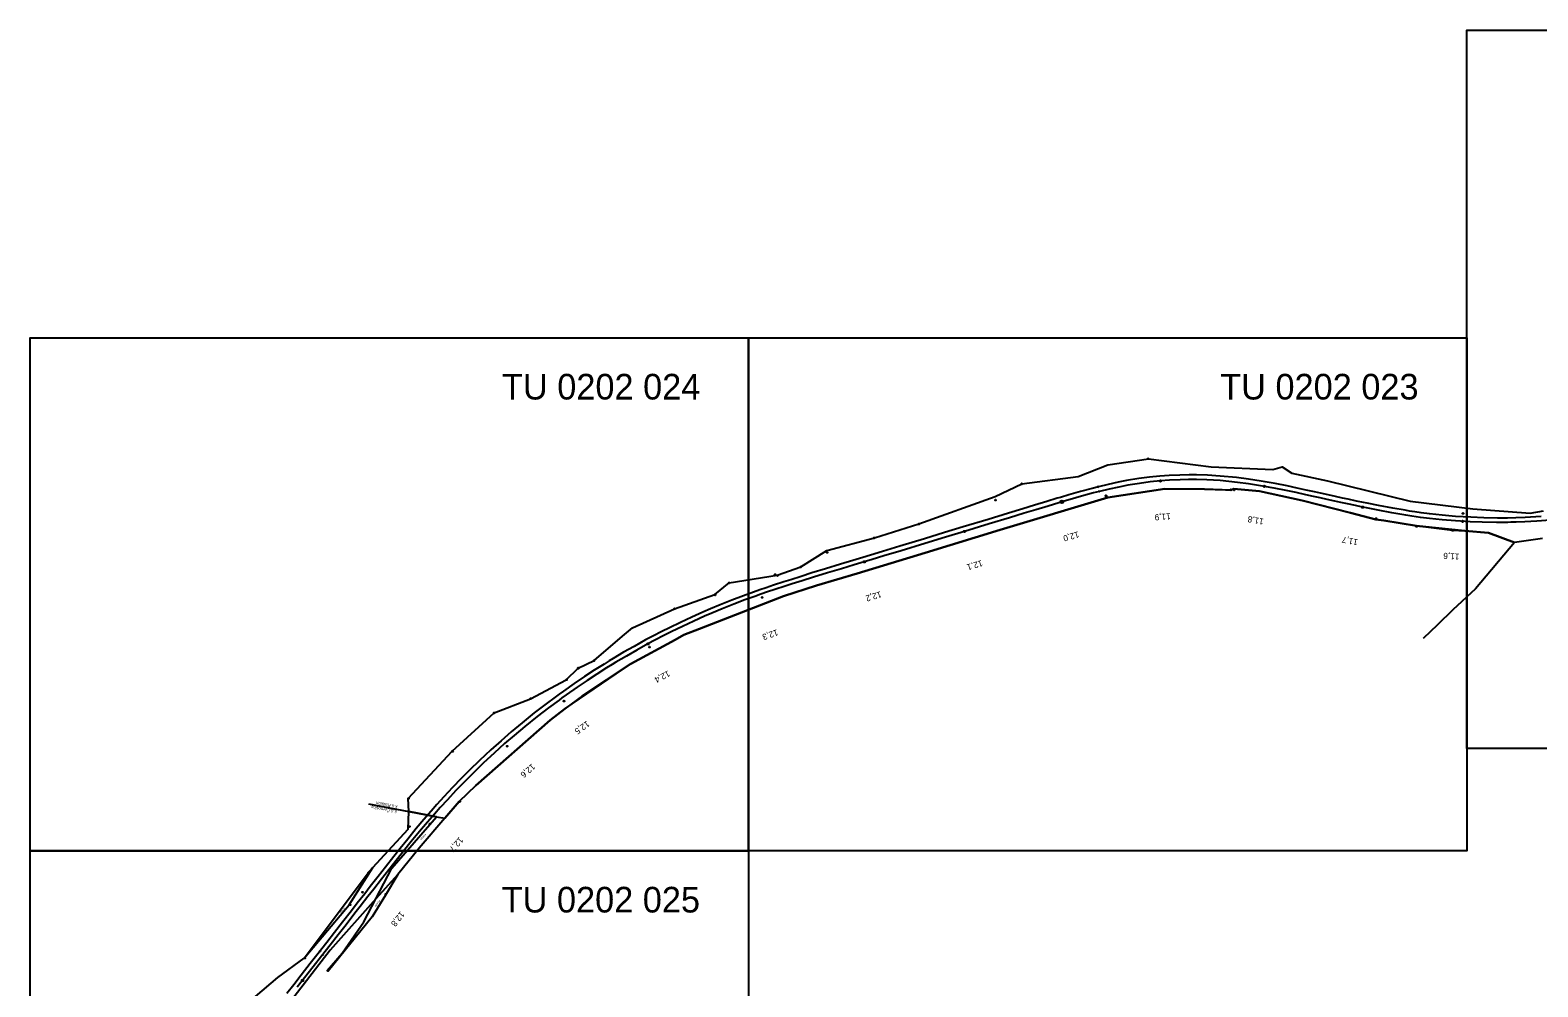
# Model space of a CAD drawing. Extents: x -768800 to -748700, y -1061452 to -1051366.
# Drawn here: x -751300 to -749831, y -1055132 to -1054200 of the extents above; entities that cross this region are included whole.
import ezdxf

# ---------------------------------------------------------------- set-up
doc = ezdxf.new("R2010")
doc.units = 0
for name, color, linetype in [('Vrstva 1', 7, 'Continuous'), ('Vrstva 2', 7, 'Continuous'), ('Vrstva 53', 7, 'Continuous'), ('Vrstva 55', 7, 'Continuous'), ('Vrstva 57', 7, 'Continuous'), ('Vrstva 7', 7, 'Continuous')]:
    doc.layers.add(name, color=color, linetype=linetype)

msp = doc.modelspace()

# ---------------------------------------------------------------- linework, layer by layer
at = {"layer": 'Vrstva 1'}
for points in [[(-749900, -1054900), (-749900, -1054200), (-749400, -1054200), (-749400, -1054900), (-749900, -1054900)], [(-751300, -1055000), (-751300, -1054500), (-750600, -1054500), (-750600, -1055000), (-751300, -1055000)], [(-750600, -1055000), (-750600, -1054500), (-749900, -1054500), (-749900, -1055000), (-750600, -1055000)], [(-749827.5, -1054674), (-749832.7, -1054674.4), (-749843.2, -1054674.9), (-749852.2, -1054675.3), (-749860.3, -1054675.5), (-749870.1, -1054675.5), (-749883.3, -1054675.3), (-749896.2, -1054674.8), (-749910.9, -1054673.9), (-749923.9, -1054672.8), (-749936.3, -1054671.4), (-749944.5, -1054670.3), (-749950.8, -1054669.4), (-749953.1, -1054669.1), (-749955.7, -1054668.7), (-749960.2, -1054668), (-749972.1, -1054666), (-749985.9, -1054663.4), (-749997.1, -1054661.2), (-750000.8, -1054660.4), (-750007.6, -1054659), (-750015.5, -1054657.3), (-750021, -1054656.1), (-750027.8, -1054654.6), (-750035, -1054653), (-750042.5, -1054651.3), (-750048.3, -1054650), (-750056.4, -1054648.3), (-750065.2, -1054646.4), (-750075.2, -1054644.3), (-750086.9, -1054642), (-750096.5, -1054640.3), (-750100.3, -1054639.6), (-750112.6, -1054637.7), (-750124.3, -1054636.1), (-750140.2, -1054634.6), (-750152.8, -1054633.8), (-750163.5, -1054633.4), (-750170.7, -1054633.4), (-750179.8, -1054633.6), (-750190, -1054634.1), (-750199.2, -1054634.7), (-750209.2, -1054635.8), (-750219.6, -1054637.1), (-750231.5, -1054639.1), (-750239.8, -1054640.7), (-750249.4, -1054642.8), (-750259, -1054645.1), (-750265, -1054646.6), (-750276.3, -1054649.7), (-750287.8, -1054653), (-750296, -1054655.4), (-750299.1, -1054656.3), (-750309.3, -1054659.4), (-750321.3, -1054663.1), (-750332.7, -1054666.5), (-750346.7, -1054670.8), (-750366.5, -1054676.8), (-750390.9, -1054684.2), (-750409, -1054689.7), (-750428.6, -1054695.7), (-750452.5, -1054703), (-750469.5, -1054708.1), (-750481.1, -1054711.7), (-750488.6, -1054714), (-750498.4, -1054716.9), (-750510.3, -1054720.6), (-750525.1, -1054725.1), (-750538.1, -1054729.1), (-750548.8, -1054732.4), (-750558.8, -1054735.6), (-750565.7, -1054737.8), (-750575.7, -1054741.1), (-750582.8, -1054743.5), (-750589, -1054745.6), (-750595.2, -1054747.8), (-750604.9, -1054751.3), (-750616.1, -1054755.6), (-750627.7, -1054760.2), (-750637.1, -1054764.1), (-750644.5, -1054767.3), (-750655.2, -1054772.1), (-750666.2, -1054777.2), (-750677.1, -1054782.5), (-750684.3, -1054786.1), (-750693.3, -1054790.7), (-750700.2, -1054794.4), (-750711.4, -1054800.6), (-750721.7, -1054806.4), (-750731.8, -1054812.4), (-750735.7, -1054814.8), (-750740.6, -1054817.8), (-750750.3, -1054823.9), (-750759.7, -1054830.1), (-750769.8, -1054836.9), (-750780.3, -1054844.2), (-750784.5, -1054847.2), (-750787, -1054849), (-750798.5, -1054857.6), (-750808.7, -1054865.5), (-750820.7, -1054875.2), (-750831.1, -1054883.9), (-750841.1, -1054892.6), (-750851, -1054901.4), (-750862, -1054911.7), (-750871.8, -1054921.3), (-750880, -1054929.5), (-750888.4, -1054938.2), (-750896.8, -1054947.2), (-750903.7, -1054954.8), (-750909.3, -1054961.2), (-750916.4, -1054969.4), (-750923.7, -1054978.1), (-750932.1, -1054988.4), (-750939.5, -1054997.7), (-750945.7, -1055005.4), (-750953.7, -1055015.7), (-750960.9, -1055024.9), (-750968.5, -1055034.6), (-750974, -1055041.8), (-750981.2, -1055051), (-750986.9, -1055058.3), (-750995.5, -1055069.3), (-751003.5, -1055079.5), (-751011, -1055089.1), (-751019.3, -1055099.9), (-751027, -1055109.7), (-751035.9, -1055121.2), (-751043.2, -1055130.4), (-751050, -1055139.1)], [(-749818.6, -1054677.6), (-749831.8, -1054678.6), (-749843.4, -1054679.3), (-749851.9, -1054679.6), (-749857.2, -1054679.7), (-749860, -1054679.8), (-749862.2, -1054679.8), (-749871.2, -1054679.9), (-749884.9, -1054679.7), (-749896.6, -1054679.3), (-749911, -1054678.4), (-749923.9, -1054677.3), (-749936.5, -1054675.9), (-749945.2, -1054674.9), (-749953.6, -1054673.6), (-749959.4, -1054672.8), (-749973.2, -1054670.4), (-749986.4, -1054668), (-749997.6, -1054665.7), (-750001.7, -1054664.9), (-750008.5, -1054663.4), (-750016.2, -1054661.8), (-750022.6, -1054660.4), (-750028.7, -1054659), (-750036, -1054657.4), (-750043, -1054655.8), (-750049.4, -1054654.4), (-750056.9, -1054652.8), (-750066.4, -1054650.7), (-750075.9, -1054648.7), (-750087.6, -1054646.4), (-750097.2, -1054644.7), (-750100.9, -1054644), (-750112.6, -1054642.2), (-750123.4, -1054640.8), (-750140.5, -1054639.1), (-750153.2, -1054638.3), (-750163.4, -1054638.1), (-750171.1, -1054638), (-750179.4, -1054638.2), (-750189.6, -1054638.7), (-750198.5, -1054639.4), (-750208.4, -1054640.4), (-750218.8, -1054641.8), (-750230.2, -1054643.6), (-750239.2, -1054645.4), (-750248.4, -1054647.3), (-750257.9, -1054649.6), (-750263.7, -1054651.1), (-750275.4, -1054654.3), (-750286.6, -1054657.5), (-750294.7, -1054659.9), (-750297.7, -1054660.8), (-750308.1, -1054663.9), (-750320, -1054667.5), (-750331.3, -1054670.9), (-750345.7, -1054675.3), (-750365.3, -1054681.3), (-750389.5, -1054688.6), (-750407.9, -1054694.2), (-750428.3, -1054700.4), (-750451.3, -1054707.4), (-750468.2, -1054712.5), (-750479.6, -1054715.9), (-750487.2, -1054718.2), (-750496.9, -1054721.1), (-750509.3, -1054724.9), (-750523, -1054729.1), (-750536.8, -1054733.3), (-750547.8, -1054736.7), (-750557.4, -1054739.7), (-750564.1, -1054741.8), (-750574.4, -1054745.2), (-750581.5, -1054747.6), (-750587.8, -1054749.8), (-750593.7, -1054751.9), (-750603.4, -1054755.4), (-750614.4, -1054759.5), (-750625.8, -1054764.1), (-750635.6, -1054768.2), (-750642.8, -1054771.3), (-750653.4, -1054776), (-750664.2, -1054781.1), (-750674.7, -1054786.2), (-750682.6, -1054790.1), (-750691.4, -1054794.6), (-750698.2, -1054798.3), (-750708.8, -1054804.2), (-750719, -1054810), (-750729.2, -1054816), (-750732.8, -1054818.2), (-750738.2, -1054821.5), (-750747.9, -1054827.7), (-750757.3, -1054833.8), (-750767.1, -1054840.5), (-750777.8, -1054848), (-750781.8, -1054850.8), (-750784.6, -1054852.9), (-750795, -1054860.6), (-750806, -1054869.1), (-750818, -1054878.7), (-750828.3, -1054887.4), (-750837.6, -1054895.4), (-750847.9, -1054904.7), (-750858.2, -1054914.2), (-750868.7, -1054924.4), (-750876.7, -1054932.5), (-750885.1, -1054941.1), (-750893.4, -1054950.1), (-750900.3, -1054957.6), (-750906.1, -1054964.2), (-750912.9, -1054972), (-750920.5, -1054981), (-750928.6, -1054990.9), (-750936.2, -1055000.3), (-750942.1, -1055007.8), (-750950.4, -1055018.4), (-750957.7, -1055027.6), (-750965.2, -1055037.3), (-750970.8, -1055044.4), (-750978.4, -1055054.3), (-750983.5, -1055060.8), (-750992.2, -1055071.9), (-751000, -1055081.9), (-751007.8, -1055091.9), (-751016, -1055102.5), (-751024.1, -1055112.8), (-751032.5, -1055123.6), (-751039.7, -1055132.9)], [(-751300, -1055500), (-751300, -1055000), (-750600, -1055000), (-750600, -1055500), (-751300, -1055500)]]:
    msp.add_lwpolyline(points, dxfattribs=at)
at = {"layer": 'Vrstva 53'}
for p, q in [((-750210.4, -1054617.7), (-750210.5, -1054617.7)), ((-750333.5, -1054642.2), (-750333.6, -1054642.3)), ((-750251.6, -1054653.8), (-750251.7, -1054653.8)), ((-750129.9, -1054648), (-750130, -1054648)), ((-750126.7, -1054648.1), (-750126.8, -1054648.1)), ((-750359.2, -1054658.1), (-750359.3, -1054658.1)), ((-750433.9, -1054681.4), (-750434, -1054681.4)), ((-749988.2, -1054676.1), (-749988.3, -1054676.1)), ((-749948.9, -1054683.6), (-749949, -1054683.6)), ((-750477.4, -1054694.9), (-750477.5, -1054694.9)), ((-750477.5, -1054694.9), (-750477.4, -1054694.9)), ((-749913.7, -1054687.5), (-749913.8, -1054687.5)), ((-750523.3, -1054709), (-750523.4, -1054709)), ((-750548.9, -1054723.2), (-750549, -1054723.2)), ((-750618.8, -1054738.7), (-750618.9, -1054738.7)), ((-750574.1, -1054730.7), (-750574, -1054730.7)), ((-750571.8, -1054731.5), (-750571.9, -1054731.6)), ((-750632.5, -1054750.4), (-750632.6, -1054750.4)), ((-750672.1, -1054763.9), (-750672.2, -1054763.9)), ((-750750.2, -1054814.5), (-750750.3, -1054814.5)), ((-750777.4, -1054833), (-750777.4, -1054833.1)), ((-750766.1, -1054821.8), (-750766, -1054821.8)), ((-750765.8, -1054822), (-750765.9, -1054822.1)), ((-750812.2, -1054851.4), (-750812.3, -1054851.5)), ((-750761.6, -1054849.1), (-750761.7, -1054849.2)), ((-750847.8, -1054865.4), (-750847.8, -1054865.5)), ((-750888.4, -1054902.9), (-750888.4, -1054902.9)), ((-750931.4, -1054948.9), (-750931.5, -1054949)), ((-750931.1, -1054961.5), (-750931.1, -1054961.6)), ((-750881.3, -1054951.9), (-750881.3, -1054952)), ((-750930.4, -1054976.2), (-750930.5, -1054976.3)), ((-750970.2, -1055021.5), (-750970.2, -1055021.5)), ((-750988.2, -1055052.4), (-750988.2, -1055052.5)), ((-750953.3, -1055042.2), (-750953.4, -1055042.3)), ((-751032.3, -1055104.5), (-751032.4, -1055104.5))]:
    msp.add_line(p, q, dxfattribs=at)
for points in [[(-750931.1, -1054961.4), (-750931.6, -1054949), (-750888.6, -1054902.8), (-750847.9, -1054865.4), (-750812.3, -1054851.7), (-750777.6, -1054833.1), (-750766, -1054821.7), (-750750.4, -1054814.4), (-750722.9, -1054790.6), (-750713, -1054782.4), (-750672.1, -1054763.9), (-750632.9, -1054750.2), (-750618.8, -1054738.6), (-750571.9, -1054731.3), (-750549.1, -1054723.1), (-750523.8, -1054707.3), (-750477.3, -1054694.7), (-750433.9, -1054681.3), (-750359.5, -1054654.7), (-750333.6, -1054642.1), (-750278.8, -1054634.9), (-750249.7, -1054623.8), (-750210.3, -1054617.7), (-750149, -1054625.5), (-750088.9, -1054628.2), (-750079.8, -1054625.6), (-750070.6, -1054631.7), (-750035.6, -1054639.4), (-749955.1, -1054659), (-749894.2, -1054666.6), (-749838.3, -1054670.7), (-749825.1, -1054668.6)], [(-749826.3, -1054695.4), (-749853.4, -1054699.5), (-749878.7, -1054689.8), (-749901.9, -1054688.1), (-749939.8, -1054684.1), (-749948.9, -1054683), (-749980.7, -1054678), (-749988.6, -1054676.8), (-750013.3, -1054670.4), (-750060.3, -1054658.4), (-750102.1, -1054649.2), (-750127, -1054647), (-750130, -1054648.4), (-750155.7, -1054647.4), (-750194.3, -1054647.2), (-750249.9, -1054655.4), (-750354.8, -1054686.9), (-750427.8, -1054709.4), (-750494, -1054729.6), (-750533.8, -1054741.3), (-750566, -1054751.8), (-750647.6, -1054783.5), (-750663.1, -1054789.5), (-750671.5, -1054794.1), (-750714.5, -1054817.7), (-750761.6, -1054848.9), (-750778.8, -1054861.6), (-750793.4, -1054872.4), (-750865.8, -1054936.1), (-750881.8, -1054951.7), (-750895.8, -1054968.2)], [(-751080.3, -1055141.9), (-751058.6, -1055123.3), (-751033.1, -1055104.6), (-750969.3, -1055019.7), (-750966, -1055016.1), (-750931.7, -1054978.8), (-750931.1, -1054961.4)], [(-750895.8, -1054968.2), (-750920.9, -1054997.3), (-750941.6, -1055022.9), (-750953.8, -1055043.1), (-750966.8, -1055064.2), (-751009.7, -1055117.3), (-751010.7, -1055116.4), (-750996.1, -1055099.7), (-750974.7, -1055069.2), (-750963, -1055046.8), (-751007.6, -1055096.7), (-751044.9, -1055145)]]:
    msp.add_lwpolyline(points, dxfattribs=at)
for centre in [(-750210.4, -1054617.7), (-750333.6, -1054642.2), (-750251.6, -1054653.8), (-750129.9, -1054648), (-750126.8, -1054648.1), (-750359.3, -1054658.1), (-750434, -1054681.4), (-749988.2, -1054676.1), (-749948.9, -1054683.6), (-750477.5, -1054694.9), (-750477.5, -1054694.9), (-749913.8, -1054687.5), (-750523.4, -1054709), (-750574, -1054730.7), (-750549, -1054723.2), (-750618.8, -1054738.7), (-750571.8, -1054731.6), (-750632.5, -1054750.4), (-750672.1, -1054763.9), (-750750.3, -1054814.5), (-750777.4, -1054833.1), (-750766, -1054821.8), (-750765.9, -1054822.1), (-750812.2, -1054851.5), (-750761.7, -1054849.2), (-750847.8, -1054865.5), (-750888.4, -1054902.9), (-750931.4, -1054949), (-750931.1, -1054961.6), (-750881.3, -1054951.9), (-750930.4, -1054976.3), (-750970.2, -1055021.5), (-750988.2, -1055052.4), (-750953.3, -1055042.2), (-751032.4, -1055104.5)]:
    msp.add_circle(centre, 0.499, dxfattribs=at)
at = {"layer": 'Vrstva 55'}
for p, q in [((-750904, -1054966.6), (-750931.1, -1054961.4)), ((-750931.1, -1054961.4), (-750904, -1054966.6)), ((-750941.6, -1055022.9), (-750963, -1055046.8))]:
    msp.add_line(p, q, dxfattribs=at)
for points in [[(-750904, -1054966.6), (-750895.8, -1054968.2), (-750881.8, -1054951.7), (-750865.8, -1054936.1), (-750793.4, -1054872.4), (-750778.8, -1054861.6), (-750714.5, -1054817.7), (-750671.5, -1054794.1), (-750663.1, -1054789.5), (-750647.6, -1054783.5), (-750566, -1054751.8), (-750533.8, -1054741.3), (-750494, -1054729.6), (-750427.8, -1054709.4), (-750354.8, -1054686.9), (-750249.9, -1054655.4), (-750194.3, -1054647.2), (-750155.7, -1054647.4), (-750135.2, -1054648.2), (-750130, -1054648.4), (-750127, -1054647), (-750102.1, -1054649.2), (-750060.3, -1054658.4), (-750013.3, -1054670.4), (-749988.6, -1054676.8), (-749980.7, -1054678), (-749948.9, -1054683), (-749939.8, -1054684.1), (-749913.8, -1054687.3), (-749901.9, -1054688.1), (-749878.7, -1054689.8), (-749853.4, -1054699.5), (-749891.5, -1054744.6), (-749913.6, -1054764.9), (-749928.5, -1054779.6), (-749942.6, -1054792.9)], [(-750970.3, -1054954.2), (-750931.1, -1054961.4)], [(-750963, -1055046.8), (-750947.6, -1055016.9), (-750904, -1054966.6), (-750895.8, -1054968.2)], [(-751033.1, -1055104.6), (-750989.1, -1055052.6), (-750966, -1055016.1)]]:
    msp.add_lwpolyline(points, dxfattribs=at)
at = {"layer": 'Vrstva 7'}
for p, q in [((-749903.7, -1054671), (-749903.8, -1054671)), ((-750586.5, -1054752.9), (-750586.6, -1054752.9)), ((-750696.5, -1054801.3), (-750696.4, -1054801.3)), ((-750779.8, -1054853.9), (-750779.9, -1054854)), ((-750835.2, -1054897.9), (-750835.3, -1054898)), ((-750910.4, -1054973.8), (-750910.5, -1054973.9)), ((-750976, -1055040.1), (-750976.1, -1055040.2))]:
    msp.add_line(p, q, dxfattribs=at)
for centre, radius in [((-750198.6, -1054639.4), 0.75), ((-750097.4, -1054644.7), 0.75), ((-750294.6, -1054659.8), 1.25), ((-750294.6, -1054659.8), 0.752), ((-750001.6, -1054664.9), 0.75), ((-749903.7, -1054671), 0.5), ((-749904.1, -1054678.8), 0.75), ((-750389.5, -1054688.6), 0.75), ((-750487.2, -1054718.2), 0.75), ((-750586.6, -1054752.9), 0.5), ((-750698.1, -1054798.2), 0.75), ((-750696.5, -1054801.3), 0.5), ((-750779.8, -1054853.9), 0.5), ((-750835.2, -1054897.9), 0.5), ((-750910.5, -1054973.8), 0.5), ((-750976, -1055040.2), 0.5), ((-751034.6, -1055126.3), 0.75)]:
    msp.add_circle(centre, radius, dxfattribs=at)

# ---------------------------------------------------------------- texts
at = {"layer": 'Vrstva 1'}
for s, rotation, p in [('2', 194.3596, (-750258.7, -1054643.7)), ('1', 194.2843, (-750257.7, -1054648.3)), ('2', 232.0698, (-751017.8, -1055096.2)), ('1', 232.0637, (-751015.2, -1055100))]:
    msp.add_text(s, height=2.5, rotation=rotation, dxfattribs=at).set_placement(p)
at = {"layer": 'Vrstva 2'}
for s, p in [('TU 0202 024', (-750840.2, -1054560)), ('TU 0202 023', (-750140.3, -1054560)), ('TU 0202 025', (-750840.5, -1055060))]:
    msp.add_text(s, height=25, dxfattribs=at).set_placement(p)
at = {"layer": 'Vrstva 55'}
for s, p in [('k.ú.Černošice', (-750942.6, -1054960.3)), ('k.ú.Radotín', (-750941.9, -1054955.6))]:
    msp.add_text(s, height=3, rotation=169.4818, dxfattribs=at).set_placement(p)
at = {"layer": 'Vrstva 57'}
for s, rotation, p in [('6192/54', 226.8664, (-750915.1, -1054983.1)), ('6192/53', 237.0062, (-750960.1, -1055047.8)), ('4180/8', 228.3621, (-750993.9, -1055055.1))]:
    msp.add_text(s, height=1.5, rotation=rotation, dxfattribs=at).set_placement(p)
at = {"layer": 'Vrstva 7'}
for s, rotation, p in [('11,9', 184.2736, (-750188.8, -1054670.8)), ('11,8', 169.7173, (-750097.5, -1054676.3)), ('12,0', 196.4707, (-750278.9, -1054688.4)), ('11,7', 168.7047, (-750005.7, -1054696.5)), ('11,6', 176.5572, (-749907.1, -1054710.3)), ('12,1', 196.8752, (-750372.8, -1054716.4)), ('12,2', 196.8957, (-750471.4, -1054746.8)), ('12,3', 199.4486, (-750572.4, -1054783.9)), ('12,4', 208.0577, (-750678.5, -1054823.9)), ('12,5', 215.6166, (-750757.5, -1054872.8)), ('12,6', 220.9606, (-750811, -1054914.5)), ('12,7', 229.2598, (-750881.8, -1054985.9)), ('12,8', 232.0221, (-750939.2, -1055058.4))]:
    msp.add_text(s, height=6, rotation=rotation, dxfattribs=at).set_placement(p)

doc.saveas('drawing.dxf')
